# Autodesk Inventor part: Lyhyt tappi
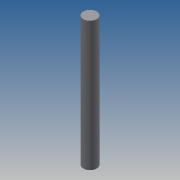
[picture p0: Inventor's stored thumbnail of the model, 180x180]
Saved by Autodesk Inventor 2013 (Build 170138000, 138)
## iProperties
Created: 2013-08
Part Number: Lyhyt tappi
Material: Generic
Document SubType Name: Modeling
Designer: Reko Tuppurainen
Density: 1 g/cm^3
Author: Reko Tuppurainen
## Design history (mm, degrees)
sketch "Sketch1"
  geometry: C1 r 6 at (0, 0); 1 further point
  constraints: 1 centre point, 1 coincident
  dimensions: "d0" = 12 diameter of C1
extrude "Extrusion1" new body sketch "Sketch1" distance "d1" = 115; taper "d2" = 0 deg
body "Solid1"
